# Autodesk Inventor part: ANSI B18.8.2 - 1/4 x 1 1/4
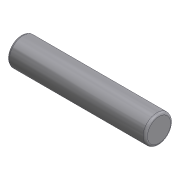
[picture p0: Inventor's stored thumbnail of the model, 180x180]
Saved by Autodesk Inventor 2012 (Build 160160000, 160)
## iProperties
Created: 2000-06
Part Number: ANSI B18.8.2 - 1/4 x 1 1/4
Material: Stainless Steel, Austenitic
Description: Pin - Hardened Ground Production Dowel
Document SubType Name: Standard Catalog Part
Standard: ANSI B18.8.2 - 1/4 x 1 1/4
Designer: Ron
Density: 1 g/cm^3
Control State: 0
Master: False
Checked Out: False
Shininess: 60.0
Length Units: 11272
Angle Units: 11279
Time Units: 11290
Mass Units: 11286
Length Display Precision: 3
Angle Display Precision: 2
Density: 0.0
Volumn: 0.0
Area: 0.0
PropertySet Name: Model Information
Author: Ron
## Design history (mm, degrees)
node "Base1"
body "Solid1"
